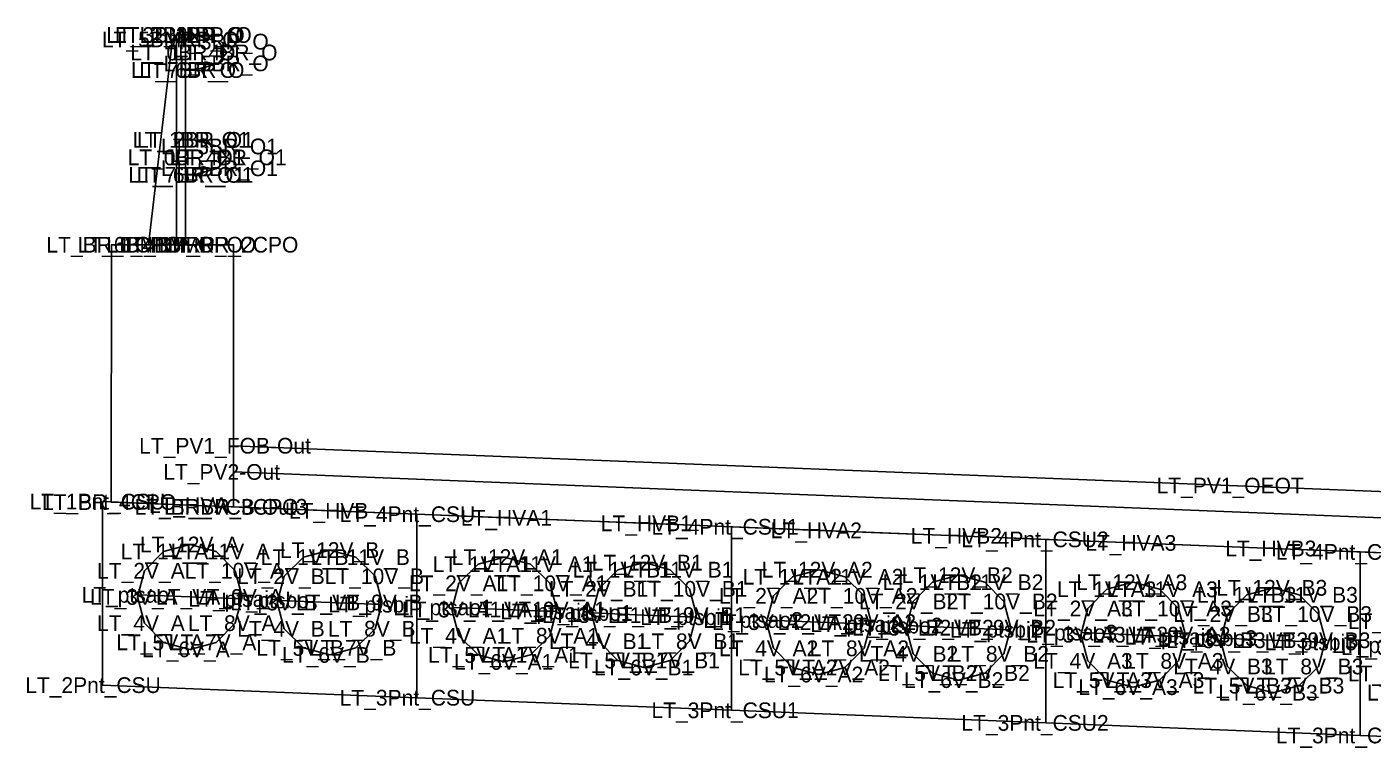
# Model space of a CAD drawing. Extents: x -26 to 1163, y -10 to 9537.
# Drawn here: x 59.53 to 72.36, y 6019.95 to 6026.82 of the extents above; entities that cross this region are included whole.
import ezdxf

# ---------------------------------------------------------------- set-up
doc = ezdxf.new("R2010")
doc.units = 0
for name, color, linetype in [('Prop CMT Bridge Metal Rail', 7, 'Continuous'), ('Prop CMT Bridge Metal Rail Post', 7, 'Continuous'), ('Prop CMT Concrete Structures', 7, 'Continuous'), ('Prop CMT Corridor Surface Symbology Blue', 7, 'Continuous'), ('Prop CMT Pvmt Course 1', 7, 'Continuous'), ('Prop CMT Pvmt Course 2', 7, 'Continuous'), ('Scratch_Level_0', 7, 'Continuous')]:
    doc.layers.add(name, color=color, linetype=linetype)

msp = doc.modelspace()

# ---------------------------------------------------------------- linework, layer by layer
at = {"layer": 'Prop CMT Bridge Metal Rail'}
for points in [[(61.041, 6026.747), (61.124, 6026.747), (61.353, 6026.684), (61.437, 6026.58)], [(61.041, 6026.58), (61.041, 6026.747)], [(61.437, 6026.58), (61.353, 6026.476), (61.124, 6026.413), (61.041, 6026.413)], [(61.041, 6026.413), (61.041, 6026.58)], [(61.041, 6025.747), (61.124, 6025.747), (61.353, 6025.684), (61.437, 6025.58)], [(61.041, 6025.58), (61.041, 6025.747)], [(61.437, 6025.58), (61.353, 6025.476), (61.124, 6025.413), (61.041, 6025.413)], [(61.041, 6025.413), (61.041, 6025.58)]]:
    msp.add_lwpolyline(points, dxfattribs=at)
at = {"layer": 'Prop CMT Bridge Metal Rail Post'}
for points in [[(60.957, 6026.747), (60.916, 6026.705), (60.687, 6024.747)], [(61.041, 6026.747), (60.957, 6026.747)], [(60.957, 6026.747), (60.957, 6024.747)], [(61.041, 6024.747), (61.041, 6026.747)]]:
    msp.add_lwpolyline(points, dxfattribs=at)
at = {"layer": 'Prop CMT Concrete Structures'}
for points in [[(61.5, 6022.247), (61.499, 6024.747), (60.334, 6024.747), (60.333, 6022.293)], [(63.25, 6022.177), (62.417, 6022.21), (61.083, 6022.263), (60.25, 6022.297)], [(60.25, 6022.297), (60.25, 6020.547)], [(60.333, 6022.293), (61.5, 6022.247)], [(66.25, 6022.057), (65.417, 6022.09), (64.083, 6022.143), (63.25, 6022.177)], [(63.25, 6022.177), (63.25, 6020.427)], [(63.25, 6020.427), (63.25, 6022.177)], [(69.25, 6021.937), (68.417, 6021.97), (67.083, 6022.023), (66.25, 6022.057)], [(66.25, 6022.057), (66.25, 6020.307)], [(66.25, 6020.307), (66.25, 6022.057)], [(72.25, 6021.817), (71.417, 6021.85), (70.083, 6021.903), (69.25, 6021.937)], [(69.25, 6021.937), (69.25, 6020.187)], [(69.25, 6020.187), (69.25, 6021.937)], [(61.083, 6021.888), (60.833, 6021.821), (60.65, 6021.638), (60.583, 6021.388)], [(61.583, 6021.388), (61.516, 6021.638), (61.333, 6021.821), (61.083, 6021.888)], [(62.417, 6021.835), (62.167, 6021.768), (61.984, 6021.585), (61.917, 6021.335)], [(62.917, 6021.335), (62.85, 6021.585), (62.667, 6021.768), (62.417, 6021.835)], [(75.25, 6021.697), (74.417, 6021.73), (73.083, 6021.783), (72.25, 6021.817)], [(72.25, 6021.817), (72.25, 6020.067)], [(72.25, 6020.067), (72.25, 6021.817)], [(64.083, 6021.768), (63.833, 6021.701), (63.65, 6021.518), (63.583, 6021.268)], [(64.583, 6021.268), (64.516, 6021.518), (64.333, 6021.701), (64.083, 6021.768)], [(65.417, 6021.715), (65.167, 6021.648), (64.984, 6021.465), (64.917, 6021.215)], [(65.917, 6021.215), (65.85, 6021.465), (65.667, 6021.648), (65.417, 6021.715)], [(67.083, 6021.648), (66.833, 6021.581), (66.65, 6021.398), (66.583, 6021.148)], [(67.583, 6021.148), (67.516, 6021.398), (67.333, 6021.581), (67.083, 6021.648)], [(68.417, 6021.595), (68.167, 6021.528), (67.984, 6021.345), (67.917, 6021.095)], [(68.917, 6021.095), (68.85, 6021.345), (68.667, 6021.528), (68.417, 6021.595)], [(70.083, 6021.528), (69.833, 6021.461), (69.65, 6021.278), (69.583, 6021.028)], [(70.583, 6021.028), (70.516, 6021.278), (70.333, 6021.461), (70.083, 6021.528)], [(71.417, 6021.475), (71.167, 6021.408), (70.984, 6021.225), (70.917, 6020.975)], [(71.917, 6020.975), (71.85, 6021.225), (71.667, 6021.408), (71.417, 6021.475)], [(60.583, 6021.388), (60.65, 6021.138), (60.833, 6020.955), (61.083, 6020.888), (61.333, 6020.955), (61.516, 6021.138), (61.583, 6021.388)], [(61.917, 6021.335), (61.984, 6021.085), (62.167, 6020.902), (62.417, 6020.835), (62.667, 6020.902), (62.85, 6021.085), (62.917, 6021.335)], [(63.583, 6021.268), (63.65, 6021.018), (63.833, 6020.835), (64.083, 6020.768), (64.333, 6020.835), (64.516, 6021.018), (64.583, 6021.268)], [(64.917, 6021.215), (64.984, 6020.965), (65.167, 6020.782), (65.417, 6020.715), (65.667, 6020.782), (65.85, 6020.965), (65.917, 6021.215)], [(66.583, 6021.148), (66.65, 6020.898), (66.833, 6020.715), (67.083, 6020.648), (67.333, 6020.715), (67.516, 6020.898), (67.583, 6021.148)], [(67.917, 6021.095), (67.984, 6020.845), (68.167, 6020.662), (68.417, 6020.595), (68.667, 6020.662), (68.85, 6020.845), (68.917, 6021.095)], [(69.583, 6021.028), (69.65, 6020.778), (69.833, 6020.595), (70.083, 6020.528), (70.333, 6020.595), (70.516, 6020.778), (70.583, 6021.028)], [(70.917, 6020.975), (70.984, 6020.725), (71.167, 6020.542), (71.417, 6020.475), (71.667, 6020.542), (71.85, 6020.725), (71.917, 6020.975)], [(60.25, 6020.547), (63.25, 6020.427)], [(63.25, 6020.427), (66.25, 6020.307)], [(66.25, 6020.307), (69.25, 6020.187)], [(69.25, 6020.187), (72.25, 6020.067)], [(72.25, 6020.067), (75.25, 6019.947)]]:
    msp.add_lwpolyline(points, dxfattribs=at)
at = {"layer": 'Prop CMT Corridor Surface Symbology Blue'}
for points in [[(61.573, 6021.369), (61.083, 6021.388), (60.593, 6021.408)], [(62.907, 6021.315), (62.417, 6021.335), (61.927, 6021.355)], [(64.573, 6021.249), (64.083, 6021.268), (63.593, 6021.288)], [(65.907, 6021.195), (65.417, 6021.215), (64.927, 6021.235)], [(67.573, 6021.129), (67.083, 6021.148), (66.593, 6021.168)], [(68.907, 6021.075), (68.417, 6021.095), (67.927, 6021.115)], [(70.573, 6021.009), (70.083, 6021.028), (69.593, 6021.048)], [(71.907, 6020.955), (71.417, 6020.975), (70.927, 6020.995)]]:
    msp.add_lwpolyline(points, dxfattribs=at)
at = {"layer": 'Prop CMT Pvmt Course 1'}
for points in [[(80, 6022.09), (71, 6022.45), (61.5, 6022.83)], [(61.5, 6022.83), (61.5, 6022.58)], [(61.5, 6022.58), (80, 6021.84)]]:
    msp.add_lwpolyline(points, dxfattribs=at)
at = {"layer": 'Prop CMT Pvmt Course 2'}
for points in [[(80, 6021.84), (61.5, 6022.58)], [(61.5, 6022.58), (61.5, 6022.247), (80, 6021.507)]]:
    msp.add_lwpolyline(points, dxfattribs=at)

# ---------------------------------------------------------------- texts
at = {"layer": 'Scratch_Level_0'}
for s, p in [('LT_3BMRP_O', (60.285, 6026.672)), ('LT_2BMRP_O', (60.369, 6026.672)), ('LT_2BR_O', (60.603, 6026.672)), ('LT_5BMRP_O', (60.244, 6026.63)), ('LT_3BR_O', (60.832, 6026.609)), ('LT_0BR_O', (60.514, 6026.505)), ('LT_5BR_O', (60.832, 6026.401)), ('LT_4BR_O', (60.916, 6026.505)), ('LT_7BR_O', (60.52, 6026.338)), ('LT_6BR_O', (60.6, 6026.338)), ('LT_1BR_O1', (60.538, 6025.672)), ('LT_2BR_O1', (60.578, 6025.672)), ('LT_0BR_O1', (60.489, 6025.505)), ('LT_3BR_O1', (60.808, 6025.609)), ('LT_4BR_O1', (60.891, 6025.505)), ('LT_5BR_O1', (60.808, 6025.401)), ('LT_7BR_O1', (60.495, 6025.338)), ('LT_6BR_O1', (60.575, 6025.338)), ('LT_BR_1CPO', (59.714, 6024.672)), ('LT_6BMRP_O', (60.011, 6024.672)), ('LT_4BMRP_O', (60.285, 6024.672)), ('LT_1BMRP_O', (60.411, 6024.672)), ('LT_BR_2CPO', (60.836, 6024.672)), ('LT_PV1_FOB-Out', (60.599, 6022.755)), ('LT_PV2-Out', (60.829, 6022.505)), ('LT_PV1_OEOT', (70.306, 6022.375)), ('LT_1Pnt_CSU', (59.554, 6022.222)), ('LT_BR_4CPO', (59.671, 6022.218)), ('LT_BR_VCB-Out3', (60.555, 6022.172)), ('LT_HVA', (60.692, 6022.188)), ('LT_BR_3CPO', (60.837, 6022.172)), ('LT_HVB', (62.028, 6022.135)), ('LT_4Pnt_CSU', (62.512, 6022.102)), ('LT_HVA1', (63.668, 6022.068)), ('LT_HVB1', (65.003, 6022.015)), ('LT_4Pnt_CSU1', (65.487, 6021.982)), ('LT_HVA2', (66.625, 6021.948)), ('LT_12V_A', (60.606, 6021.813)), ('LT_HVB2', (67.961, 6021.895)), ('LT_4Pnt_CSU2', (68.444, 6021.862)), ('LT_HVA3', (69.625, 6021.828)), ('LT_HVB3', (70.961, 6021.775)), ('LT_1V_A', (60.423, 6021.746)), ('LT_11V_A', (60.899, 6021.746)), ('LT_1V_B', (61.759, 6021.693)), ('LT_12V_B', (61.942, 6021.76)), ('LT_11V_B', (62.234, 6021.693)), ('LT_12V_A1', (63.581, 6021.693)), ('LT_4Pnt_CSU3', (71.444, 6021.742)), ('LT_2V_A', (60.198, 6021.563)), ('LT_10V_A', (61.033, 6021.563)), ('LT_1V_A1', (63.399, 6021.626)), ('LT_11V_A1', (63.874, 6021.626)), ('LT_1V_B1', (64.734, 6021.573)), ('LT_12V_B1', (64.917, 6021.64)), ('LT_11V_B1', (65.21, 6021.573)), ('LT_12V_A2', (66.539, 6021.573)), ('LT_12V_B2', (67.875, 6021.52)), ('LT_2V_B', (61.534, 6021.51)), ('LT_10V_B', (62.369, 6021.51)), ('LT_2V_A1', (63.173, 6021.443)), ('LT_10V_A1', (64.008, 6021.443)), ('LT_2V_B1', (64.509, 6021.39)), ('LT_10V_B1', (65.344, 6021.39)), ('LT_1V_A2', (66.356, 6021.506)), ('LT_11V_A2', (66.831, 6021.506)), ('LT_1V_B2', (67.692, 6021.453)), ('LT_11V_B2', (68.167, 6021.453)), ('LT_12V_A3', (69.539, 6021.453)), ('LT_12V_B3', (70.875, 6021.4)), ('LT_ptsao', (60.049, 6021.333)), ('LT_3V_A', (60.131, 6021.313)), ('LT_VA', (60.76, 6021.313)), ('LT_ptsai', (61.069, 6021.294)), ('LT_9V_A', (61.131, 6021.313)), ('LT_ptsbo', (61.383, 6021.28)), ('LT_2V_A2', (66.131, 6021.323)), ('LT_10V_A2', (66.966, 6021.323)), ('LT_2V_B2', (67.466, 6021.27)), ('LT_10V_B2', (68.302, 6021.27)), ('LT_1V_A3', (69.356, 6021.386)), ('LT_11V_A3', (69.831, 6021.386)), ('LT_1V_B3', (70.692, 6021.333)), ('LT_11V_B3', (71.167, 6021.333)), ('LT_3V_B', (61.467, 6021.26)), ('LT_VB', (62.095, 6021.26)), ('LT_ptsbi', (62.404, 6021.24)), ('LT_9V_B', (62.467, 6021.26)), ('LT_ptsao1', (63.024, 6021.213)), ('LT_3V_A1', (63.106, 6021.193)), ('LT_VA1', (63.735, 6021.193)), ('LT_ptsai1', (64.044, 6021.174)), ('LT_9V_A1', (64.106, 6021.193)), ('LT_ptsbo1', (64.359, 6021.16)), ('LT_3V_B1', (64.442, 6021.14)), ('LT_VB1', (65.071, 6021.14)), ('LT_9V_B1', (65.442, 6021.14)), ('LT_2V_A3', (69.131, 6021.203)), ('LT_10V_A3', (69.966, 6021.203)), ('LT_2V_B3', (70.466, 6021.15)), ('LT_10V_B3', (71.302, 6021.15)), ('LT_4V_A', (60.198, 6021.063)), ('LT_8V_A', (61.064, 6021.063)), ('LT_4V_B', (61.534, 6021.01)), ('LT_8V_B', (62.4, 6021.01)), ('LT_ptsbi1', (65.379, 6021.12)), ('LT_ptsao2', (65.982, 6021.093)), ('LT_3V_A2', (66.064, 6021.073)), ('LT_VA2', (66.692, 6021.073)), ('LT_ptsai2', (67.002, 6021.054)), ('LT_9V_A2', (67.064, 6021.073)), ('LT_ptsbo2', (67.316, 6021.04)), ('LT_3V_B2', (67.399, 6021.02)), ('LT_VB2', (68.028, 6021.02)), ('LT_ptsbi2', (68.336, 6021)), ('LT_9V_B2', (68.399, 6021.02)), ('LT_2V_A4', (72.131, 6021.083)), ('LT_5V_A', (60.381, 6020.88)), ('LT_7V_A', (60.881, 6020.88)), ('LT_4V_A1', (63.173, 6020.943)), ('LT_8V_A1', (64.039, 6020.943)), ('LT_4V_B1', (64.509, 6020.89)), ('LT_8V_B1', (65.375, 6020.89)), ('LT_ptsao3', (68.982, 6020.973)), ('LT_3V_A3', (69.064, 6020.953)), ('LT_VA3', (69.692, 6020.953)), ('LT_ptsai3', (70.002, 6020.934)), ('LT_9V_A3', (70.064, 6020.953)), ('LT_ptsbo3', (70.316, 6020.92)), ('LT_3V_B3', (70.399, 6020.9)), ('LT_VB3', (71.028, 6020.9)), ('LT_ptsbi3', (71.336, 6020.88)), ('LT_9V_B3', (71.399, 6020.9)), ('LT_6V_A', (60.627, 6020.813)), ('LT_5V_B', (61.717, 6020.827)), ('LT_6V_B', (61.963, 6020.76)), ('LT_7V_B', (62.217, 6020.827)), ('LT_5V_A1', (63.356, 6020.76)), ('LT_7V_A1', (63.856, 6020.76)), ('LT_4V_A2', (66.131, 6020.823)), ('LT_8V_A2', (66.997, 6020.823)), ('LT_4V_B2', (67.466, 6020.77)), ('LT_8V_B2', (68.332, 6020.77)), ('LT_ptsao4', (71.982, 6020.853)), ('LT_3V_A4', (72.064, 6020.833)), ('LT_6V_A1', (63.603, 6020.693)), ('LT_5V_B1', (64.692, 6020.707)), ('LT_6V_B1', (64.938, 6020.64)), ('LT_7V_B1', (65.192, 6020.707)), ('LT_5V_A2', (66.314, 6020.64)), ('LT_7V_A2', (66.814, 6020.64)), ('LT_4V_A3', (69.131, 6020.703)), ('LT_8V_A3', (69.997, 6020.703)), ('LT_4V_B3', (70.466, 6020.65)), ('LT_8V_B3', (71.332, 6020.65)), ('LT_6V_A2', (66.56, 6020.573)), ('LT_5V_B2', (67.649, 6020.587)), ('LT_6V_B2', (67.896, 6020.52)), ('LT_7V_B2', (68.149, 6020.587)), ('LT_5V_A3', (69.314, 6020.52)), ('LT_7V_A3', (69.814, 6020.52)), ('LT_4V_A4', (72.131, 6020.583)), ('LT_2Pnt_CSU', (59.512, 6020.472)), ('LT_6V_A3', (69.56, 6020.453)), ('LT_5V_B3', (70.649, 6020.467)), ('LT_6V_B3', (70.896, 6020.4)), ('LT_7V_B3', (71.149, 6020.467)), ('LT_5V_A4', (72.314, 6020.4)), ('LT_3Pnt_CSU', (62.512, 6020.352)), ('LT_3Pnt_CSU1', (65.487, 6020.232)), ('LT_3Pnt_CSU2', (68.444, 6020.112)), ('LT_3Pnt_CSU3', (71.444, 6019.992))]:
    msp.add_text(s, height=0.15, dxfattribs=at).set_placement(p)

doc.saveas('drawing.dxf')
